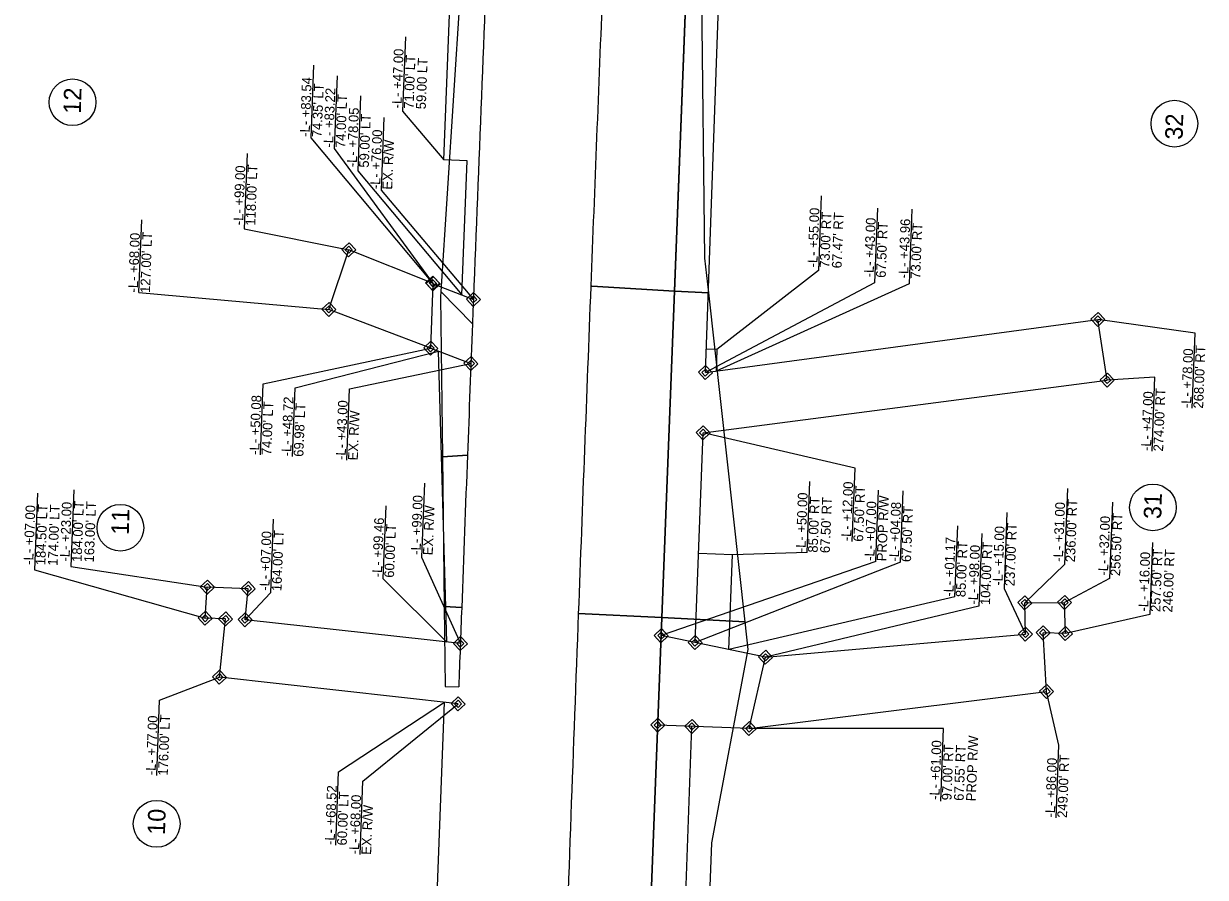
# Model space of a CAD drawing. Extents: x 2097272 to 2098144, y 685104 to 689282.
# Drawn here: x 2097469 to 2098076, y 687399 to 687838 of the extents above; entities that cross this region are included whole.
import ezdxf

# ---------------------------------------------------------------- set-up
doc = ezdxf.new("R2010")
doc.units = 0
for name, color, linetype in [('Prop Easement Construction', 7, 'Continuous'), ('Prop Easement Construction Station Offsets', 7, 'Continuous'), ('Prop Easement Permanent Drainage Utility', 7, 'Continuous'), ('Prop Easement Permanent Drainage Utility Station Offsets', 7, 'Continuous'), ('Prop Easement Permanent Utility', 7, 'Continuous'), ('Prop Easement Permanent Utility Station Offsets', 7, 'Continuous'), ('Prop Parcel Number CELL', 7, 'Continuous'), ('Prop ROW Marker CELL', 7, 'Continuous'), ('Prop ROW Permanent Easement CELL', 7, 'Continuous'), ('Prop ROW RW Lines', 7, 'Continuous'), ('Scratch_Level_3', 7, 'Continuous'), ('Scratch_Level_6', 7, 'Continuous')]:
    doc.layers.add(name, color=color, linetype=linetype)

msp = doc.modelspace()

# ---------------------------------------------------------------- linework, layer by layer
at = {"layer": 'Prop Easement Construction'}
for p, q in [((2097685.03, 687767.87), (2097689.17, 687875.79)), ((2097697.02, 687767.41), (2097685.03, 687767.87)), ((2097694.38, 687698.51), (2097697.02, 687767.41)), ((2097825.4, 687670.42), (2097819.87, 687670.63)), ((2097686.53, 687520.09), (2097682.28, 687669.63)), ((2097825.4, 687670.42), (2097824.97, 687659.39)), ((2097833.37, 687565.03), (2097815.88, 687565.7)), ((2097831.49, 687516.24), (2097833.37, 687565.03)), ((2097669.31, 687070.96), (2097685.35, 687489.17))]:
    msp.add_line(p, q, dxfattribs=at)
at = {"layer": 'Prop Easement Construction Station Offsets'}
for p, q in [((2097665.28, 687831.2), (2097663.81, 687792.87)), ((2097642.28, 687800.87), (2097640.8, 687762.32)), ((2097663.81, 687792.87), (2097685.03, 687767.87)), ((2097640.8, 687762.32), (2097694.38, 687698.51)), ((2097879.01, 687749.5), (2097877.54, 687711.11)), ((2097925.58, 687742.64), (2097924.11, 687704.25)), ((2097877.54, 687711.11), (2097825.4, 687670.42)), ((2097924.11, 687704.25), (2097824.97, 687659.39)), ((2097608.58, 687650.77), (2097682.28, 687669.63)), ((2097607.23, 687615.48), (2097608.58, 687650.77)), ((2097871.71, 687566.17), (2097873.11, 687602.61)), ((2097655.21, 687590.14), (2097653.78, 687552.81)), ((2097947.71, 687543.32), (2097949.11, 687579.77)), ((2097871.71, 687566.16), (2097833.37, 687565.03)), ((2097653.78, 687552.81), (2097686.53, 687520.09)), ((2097947.71, 687543.32), (2097831.49, 687516.24)), ((2097630.97, 687453.42), (2097685.35, 687489.17)), ((2097629.52, 687415.74), (2097630.97, 687453.42))]:
    msp.add_line(p, q, dxfattribs=at)
at = {"layer": 'Prop Easement Permanent Drainage Utility'}
for p, q in [((2097678.32, 687671.14), (2097679.59, 687704.25)), ((2097679.59, 687704.25), (2097700.26, 687696.23)), ((2097678.32, 687671.14), (2097698.98, 687663.26)), ((2097850.36, 687512.34), (2097796.74, 687523.41)), ((2097841.95, 687475.64), (2097850.36, 687512.34)), ((2097841.95, 687475.64), (2097794.98, 687477.44))]:
    msp.add_line(p, q, dxfattribs=at)
at = {"layer": 'Prop Easement Permanent Drainage Utility Station Offsets'}
for p, q in [((2097630.19, 687811.06), (2097628.75, 687773.67)), ((2097654.27, 687789.66), (2097652.83, 687752.27)), ((2097628.75, 687773.67), (2097679.59, 687704.25)), ((2097652.83, 687752.27), (2097700.26, 687696.23)), ((2097592.17, 687652.87), (2097678.32, 687671.14)), ((2097636.58, 687650.21), (2097698.98, 687663.26)), ((2097590.77, 687616.27), (2097592.17, 687652.87)), ((2097635.18, 687613.61), (2097636.58, 687650.21)), ((2097907.09, 687561.76), (2097908.49, 687598.2)), ((2097961.45, 687575.99), (2097960.02, 687538.56)), ((2097907.08, 687561.52), (2097796.74, 687523.41)), ((2097960.02, 687538.56), (2097850.36, 687512.34)), ((2097941.79, 687475.76), (2097841.95, 687475.64)), ((2097940.36, 687438.43), (2097941.79, 687475.76))]:
    msp.add_line(p, q, dxfattribs=at)
at = {"layer": 'Prop Easement Permanent Utility'}
for p, q in [((2097819.44, 687658.64), (2097827.26, 687875.5)), ((2097626.04, 687691.07), (2097636.22, 687721.7)), ((2097678.32, 687671.14), (2097626.04, 687691.07)), ((2097819.44, 687658.64), (2098021.14, 687685.93)), ((2098025.94, 687654.72), (2098021.14, 687685.93)), ((2097818.25, 687627.66), (2098025.94, 687654.72)), ((2097814.12, 687519.82), (2097818.25, 687627.66)), ((2097562.42, 687532.39), (2097563.53, 687548.36)), ((2097584.51, 687547.56), (2097563.53, 687548.36)), ((2097582.9, 687531.61), (2097584.51, 687547.56)), ((2097983.53, 687540.26), (2098004.05, 687540.47)), ((2097983.91, 687524.23), (2097983.53, 687540.26)), ((2098004.44, 687524.45), (2098004.05, 687540.47)), ((2097572.91, 687531.99), (2097562.42, 687532.39)), ((2097569.76, 687502.09), (2097572.91, 687531.99)), ((2097693.54, 687519.36), (2097582.9, 687531.61)), ((2097994.79, 687494.8), (2097992.94, 687524.89)), ((2098004.44, 687524.45), (2097992.94, 687524.89)), ((2097850.36, 687512.34), (2097983.91, 687524.23)), ((2097692.39, 687488.38), (2097569.76, 687502.09)), ((2097841.95, 687475.64), (2097994.79, 687494.8)), ((2097789.62, 686827.81), (2097812.51, 687476.77))]:
    msp.add_line(p, q, dxfattribs=at)
msp.add_lwpolyline([(2097679.59, 687704.25), (2097679.25, 687704.59), (2097636.22, 687721.7)], dxfattribs=at)
at = {"layer": 'Prop Easement Permanent Utility Station Offsets'}
for p, q in [((2097618.09, 687816.58), (2097616.66, 687779.19)), ((2097616.66, 687779.19), (2097679.25, 687704.59)), ((2097583.92, 687771.19), (2097582.44, 687732.49)), ((2097907.83, 687743.16), (2097906.36, 687704.77)), ((2097528.4, 687699.67), (2097529.83, 687737.06)), ((2097582.44, 687732.49), (2097636.22, 687721.7)), ((2097906.36, 687704.77), (2097819.44, 687658.64)), ((2097528.4, 687699.67), (2097626.04, 687691.07)), ((2098071.04, 687678.8), (2098021.14, 687685.93)), ((2098069.56, 687640.24), (2098071.04, 687678.8)), ((2098050.46, 687656.3), (2098025.94, 687654.72)), ((2098049, 687618.22), (2098050.46, 687656.3)), ((2097896.37, 687609.5), (2097818.25, 687627.66)), ((2097894.92, 687571.84), (2097896.37, 687609.5)), ((2097494.97, 687598.33), (2097493.46, 687558.91)), ((2097675.1, 687601.79), (2097673.65, 687563.82)), ((2097919.7, 687561.39), (2097921.1, 687597.84)), ((2098005.5, 687599.1), (2098004, 687559.95)), ((2097476.31, 687596.65), (2097474.8, 687557.22)), ((2098028.66, 687591.97), (2098027.16, 687552.83)), ((2097974.4, 687586.78), (2097972.9, 687547.63)), ((2097597.38, 687583.31), (2097595.93, 687545.34)), ((2098049.2, 687571.26), (2098047.78, 687534.36)), ((2097673.65, 687563.82), (2097693.54, 687519.36)), ((2097919.69, 687561.16), (2097814.12, 687519.82)), ((2097474.8, 687557.22), (2097562.42, 687532.39)), ((2097493.46, 687558.91), (2097563.53, 687548.36)), ((2098004, 687559.95), (2097983.53, 687540.26)), ((2098027.16, 687552.83), (2098004.05, 687540.47)), ((2097595.93, 687545.34), (2097582.9, 687531.61)), ((2097972.9, 687547.63), (2097983.91, 687524.23)), ((2098047.78, 687534.36), (2098004.44, 687524.45)), ((2097539.01, 687490.2), (2097569.76, 687502.09)), ((2098001.06, 687467.11), (2097994.79, 687494.8)), ((2097537.53, 687451.61), (2097539.01, 687490.2)), ((2097643.48, 687448.63), (2097692.39, 687488.38)), ((2097999.63, 687429.88), (2098001.06, 687467.11)), ((2097642.04, 687410.95), (2097643.48, 687448.63))]:
    msp.add_line(p, q, dxfattribs=at)
at = {"layer": 'Prop Parcel Number CELL'}
for centre in [(2097494.26, 687797.52), (2098060.47, 687786.52), (2098049.41, 687589.33), (2097518.84, 687578.87), (2097537.49, 687426.71)]:
    msp.add_circle(centre, 12, dxfattribs=at)
at = {"layer": 'Prop ROW Marker CELL'}
for p, q in [((2097636.22, 687721.7), (2097636.22, 687721.7)), ((2097679.25, 687704.59), (2097679.25, 687704.59)), ((2097626.04, 687691.07), (2097626.04, 687691.07)), ((2098021.14, 687685.93), (2098021.14, 687685.93)), ((2097819.44, 687658.64), (2097819.44, 687658.64)), ((2098025.94, 687654.72), (2098025.94, 687654.72)), ((2097563.53, 687548.36), (2097563.53, 687548.36)), ((2097584.51, 687547.56), (2097584.51, 687547.56)), ((2097983.53, 687540.26), (2097983.53, 687540.26)), ((2098004.05, 687540.47), (2098004.05, 687540.47)), ((2097562.42, 687532.39), (2097562.42, 687532.39)), ((2097572.91, 687531.99), (2097572.91, 687531.99)), ((2097582.9, 687531.61), (2097582.9, 687531.61)), ((2097992.94, 687524.89), (2097992.94, 687524.89)), ((2097693.54, 687519.36), (2097693.54, 687519.36)), ((2097796.74, 687523.41), (2097796.74, 687523.41)), ((2097814.12, 687519.82), (2097814.12, 687519.82)), ((2097983.91, 687524.23), (2097983.91, 687524.23)), ((2098004.44, 687524.45), (2098004.44, 687524.45)), ((2097850.36, 687512.34), (2097850.36, 687512.34)), ((2097569.76, 687502.09), (2097569.76, 687502.09)), ((2097994.79, 687494.8), (2097994.79, 687494.8)), ((2097692.39, 687488.38), (2097692.39, 687488.38)), ((2097794.98, 687477.44), (2097794.98, 687477.44)), ((2097812.51, 687476.77), (2097812.51, 687476.77)), ((2097841.95, 687475.64), (2097841.95, 687475.64))]:
    msp.add_line(p, q, dxfattribs=at)
at = {"layer": 'Prop ROW Permanent Easement CELL'}
for p, q in [((2097679.59, 687704.25), (2097679.59, 687704.25)), ((2097700.26, 687696.23), (2097700.26, 687696.23)), ((2097678.32, 687671.14), (2097678.32, 687671.14)), ((2097698.98, 687663.26), (2097698.98, 687663.26)), ((2097818.25, 687627.66), (2097818.25, 687627.66))]:
    msp.add_line(p, q, dxfattribs=at)
for points in [[(2097632.63, 687721.81), (2097636.33, 687725.3), (2097639.82, 687721.6), (2097636.12, 687718.11)], [(2097634.43, 687721.76), (2097636.28, 687723.5), (2097638.02, 687721.65), (2097636.17, 687719.91)], [(2097675.66, 687704.69), (2097679.36, 687708.18), (2097682.85, 687704.48), (2097679.15, 687700.99)], [(2097675.99, 687704.35), (2097679.69, 687707.85), (2097683.19, 687704.14), (2097679.48, 687700.65)], [(2097677.46, 687704.64), (2097679.31, 687706.39), (2097681.05, 687704.53), (2097679.2, 687702.79)], [(2097677.79, 687704.3), (2097679.64, 687706.05), (2097681.39, 687704.19), (2097679.54, 687702.45)], [(2097696.66, 687696.34), (2097700.36, 687699.83), (2097703.85, 687696.13), (2097700.15, 687692.63)], [(2097698.46, 687696.28), (2097700.31, 687698.03), (2097702.05, 687696.18), (2097700.2, 687694.43)], [(2097622.44, 687691.18), (2097626.15, 687694.67), (2097629.64, 687690.97), (2097625.94, 687687.47)], [(2097624.24, 687691.12), (2097626.1, 687692.87), (2097627.84, 687691.02), (2097625.99, 687689.27)], [(2098017.54, 687686.03), (2098021.24, 687689.53), (2098024.73, 687685.82), (2098021.03, 687682.33)], [(2098019.34, 687685.98), (2098021.19, 687687.73), (2098022.93, 687685.87), (2098021.08, 687684.13)], [(2097674.72, 687671.24), (2097678.42, 687674.74), (2097681.92, 687671.03), (2097678.21, 687667.54)], [(2097676.52, 687671.19), (2097678.37, 687672.94), (2097680.12, 687671.08), (2097678.27, 687669.34)], [(2097695.38, 687663.36), (2097699.09, 687666.85), (2097702.58, 687663.15), (2097698.88, 687659.66)], [(2097697.18, 687663.31), (2097699.04, 687665.06), (2097700.78, 687663.2), (2097698.93, 687661.46)], [(2097815.84, 687658.74), (2097819.55, 687662.23), (2097823.04, 687658.53), (2097819.34, 687655.04)], [(2097817.64, 687658.69), (2097819.49, 687660.44), (2097821.24, 687658.58), (2097819.39, 687656.84)], [(2098022.35, 687654.82), (2098026.05, 687658.32), (2098029.54, 687654.62), (2098025.84, 687651.12)], [(2098024.14, 687654.77), (2098026, 687656.52), (2098027.74, 687654.67), (2098025.89, 687652.92)], [(2097814.66, 687627.76), (2097818.36, 687631.26), (2097821.85, 687627.56), (2097818.15, 687624.06)], [(2097816.45, 687627.71), (2097818.31, 687629.46), (2097820.05, 687627.61), (2097818.2, 687625.86)], [(2097559.93, 687548.47), (2097563.63, 687551.96), (2097567.13, 687548.26), (2097563.42, 687544.76)], [(2097561.73, 687548.42), (2097563.58, 687550.16), (2097565.33, 687548.31), (2097563.48, 687546.56)], [(2097580.91, 687547.66), (2097584.62, 687551.16), (2097588.11, 687547.45), (2097584.41, 687543.96)], [(2097582.71, 687547.61), (2097584.57, 687549.36), (2097586.31, 687547.51), (2097584.46, 687545.76)], [(2097979.93, 687540.37), (2097983.63, 687543.86), (2097987.12, 687540.16), (2097983.42, 687536.66)], [(2098000.45, 687540.58), (2098004.15, 687544.07), (2098007.65, 687540.37), (2098003.95, 687536.88)], [(2097981.73, 687540.31), (2097983.58, 687542.06), (2097985.32, 687540.21), (2097983.47, 687538.46)], [(2098002.25, 687540.53), (2098004.1, 687542.27), (2098005.85, 687540.42), (2098004, 687538.68)], [(2097558.82, 687532.5), (2097562.52, 687535.99), (2097566.01, 687532.29), (2097562.31, 687528.8)], [(2097560.62, 687532.45), (2097562.47, 687534.19), (2097564.21, 687532.34), (2097562.36, 687530.59)], [(2097569.31, 687532.1), (2097573.01, 687535.59), (2097576.51, 687531.89), (2097572.8, 687528.39)], [(2097571.11, 687532.04), (2097572.96, 687533.79), (2097574.71, 687531.94), (2097572.86, 687530.19)], [(2097579.3, 687531.71), (2097583.01, 687535.21), (2097586.5, 687531.5), (2097582.8, 687528.01)], [(2097581.1, 687531.66), (2097582.95, 687533.41), (2097584.7, 687531.56), (2097582.85, 687529.81)], [(2097793.14, 687523.51), (2097796.85, 687527.01), (2097800.34, 687523.3), (2097796.64, 687519.81)], [(2097794.94, 687523.46), (2097796.8, 687525.21), (2097798.54, 687523.35), (2097796.69, 687521.61)], [(2097980.31, 687524.34), (2097984.02, 687527.83), (2097987.51, 687524.13), (2097983.81, 687520.64)], [(2097982.11, 687524.29), (2097983.96, 687526.03), (2097985.71, 687524.18), (2097983.86, 687522.44)], [(2097989.35, 687524.99), (2097993.05, 687528.49), (2097996.54, 687524.78), (2097992.84, 687521.29)], [(2097991.14, 687524.94), (2097993, 687526.69), (2097994.74, 687524.84), (2097992.89, 687523.09)], [(2098000.84, 687524.55), (2098004.54, 687528.05), (2098008.03, 687524.34), (2098004.33, 687520.85)], [(2098002.64, 687524.5), (2098004.49, 687526.25), (2098006.23, 687524.4), (2098004.38, 687522.65)], [(2097689.94, 687519.46), (2097693.64, 687522.96), (2097697.14, 687519.25), (2097693.43, 687515.76)], [(2097691.74, 687519.41), (2097693.59, 687521.16), (2097695.34, 687519.31), (2097693.49, 687517.56)], [(2097810.52, 687519.93), (2097814.22, 687523.42), (2097817.72, 687519.72), (2097814.01, 687516.22)], [(2097812.32, 687519.87), (2097814.17, 687521.62), (2097815.92, 687519.77), (2097814.07, 687518.02)], [(2097846.76, 687512.45), (2097850.46, 687515.94), (2097853.96, 687512.24), (2097850.25, 687508.75)], [(2097848.56, 687512.4), (2097850.41, 687514.14), (2097852.16, 687512.29), (2097850.31, 687510.54)], [(2097566.16, 687502.19), (2097569.86, 687505.69), (2097573.36, 687501.99), (2097569.66, 687498.49)], [(2097567.96, 687502.14), (2097569.81, 687503.89), (2097571.56, 687502.04), (2097569.71, 687500.29)], [(2097991.19, 687494.9), (2097994.9, 687498.39), (2097998.39, 687494.69), (2097994.69, 687491.2)], [(2097992.99, 687494.85), (2097994.84, 687496.6), (2097996.59, 687494.74), (2097994.74, 687493)], [(2097688.79, 687488.49), (2097692.49, 687491.98), (2097695.99, 687488.28), (2097692.28, 687484.78)], [(2097690.59, 687488.43), (2097692.44, 687490.18), (2097694.19, 687488.33), (2097692.34, 687486.58)], [(2097791.38, 687477.55), (2097795.08, 687481.04), (2097798.58, 687477.34), (2097794.88, 687473.84)], [(2097793.18, 687477.49), (2097795.03, 687479.24), (2097796.78, 687477.39), (2097794.93, 687475.64)], [(2097808.91, 687476.87), (2097812.62, 687480.37), (2097816.11, 687476.66), (2097812.41, 687473.17)], [(2097810.71, 687476.82), (2097812.56, 687478.57), (2097814.31, 687476.72), (2097812.46, 687474.97)], [(2097838.35, 687475.74), (2097842.05, 687479.24), (2097845.54, 687475.54), (2097841.84, 687472.04)], [(2097840.15, 687475.69), (2097842, 687477.44), (2097843.74, 687475.59), (2097841.89, 687473.84)]]:
    msp.add_lwpolyline(points, close=True, dxfattribs=at)
at = {"layer": 'Prop ROW RW Lines'}
msp.add_line((2097775.94, 686980.56), (2097815.64, 688016.04), dxfattribs=at)
at = {"layer": 'Scratch_Level_3'}
for p, q in [((2097803.54, 687700.51), (2097809.42, 687853.94)), ((2097760.56, 687702.99), (2097761.1, 687702.95)), ((2097761.1, 687702.95), (2097760.56, 687702.99)), ((2097761.1, 687702.95), (2097803.54, 687700.51)), ((2097803.54, 687700.51), (2097761.1, 687702.95)), ((2097797.1, 687532.67), (2097803.54, 687700.51)), ((2097754.16, 687534.79), (2097797.1, 687532.67)), ((2097797.1, 687532.67), (2097754.16, 687534.79)), ((2097776.58, 686997.78), (2097797.1, 687532.67))]:
    msp.add_line(p, q, dxfattribs=at)
for start, end in [(177.7042161, 177.7780686), (177.7780686, 177.8592491), (177.8592491, 177.9594601)]:
    msp.add_arc((2216468.39, 683097.18), 118797.14, start, end, dxfattribs=at)
at = {"layer": 'Scratch_Level_6'}
for p, q in [((2097695.97, 687891.79), (2097683.51, 687700.25)), ((2097809.42, 687853.94), (2097803.54, 687700.51)), ((2097819.19, 687717.38), (2097817.61, 687853.54)), ((2097821.18, 687699.5), (2097819.19, 687717.38)), ((2097683.51, 687700.25), (2097683.33, 687697.57)), ((2097683.33, 687697.57), (2097684.29, 687615.29)), ((2097699.77, 687683.69), (2097683.51, 687700.25)), ((2097683.51, 687700.25), (2097699.77, 687683.69)), ((2097803.54, 687700.51), (2097797.1, 687532.67)), ((2097803.54, 687700.51), (2097821.18, 687699.5)), ((2097821.18, 687699.5), (2097803.54, 687700.51)), ((2097839.93, 687530.55), (2097821.18, 687699.5)), ((2097697.18, 687616.14), (2097684.29, 687615.29)), ((2097684.29, 687615.29), (2097697.18, 687616.14)), ((2097684.29, 687615.29), (2097685.19, 687538.36)), ((2097694.23, 687537.8), (2097685.19, 687538.36)), ((2097685.19, 687538.36), (2097685.66, 687497.33)), ((2097685.19, 687538.36), (2097694.23, 687537.8)), ((2097797.1, 687532.67), (2097776.58, 686997.78)), ((2097797.1, 687532.67), (2097839.93, 687530.55)), ((2097839.93, 687530.55), (2097797.1, 687532.67)), ((2097841.51, 687516.38), (2097839.93, 687530.55)), ((2097822.69, 687417.02), (2097841.51, 687516.38)), ((2097685.66, 687497.33), (2097692.71, 687497.06)), ((2097818.85, 687317.1), (2097822.69, 687417.02))]:
    msp.add_line(p, q, dxfattribs=at)
for start, end in [(177.6883627, 177.7884999), (177.7884999, 177.8210849), (177.8210849, 177.8588768), (177.8588768, 177.8785279)]:
    msp.add_arc((2216468.39, 683097.18), 118857.14, start, end, dxfattribs=at)

# ---------------------------------------------------------------- texts
at = {"layer": 'Prop Easement Construction Station Offsets'}
for s, p in [('-L- +47.00', (2097663.24, 687794.31)), ("71.00' LT", (2097669.48, 687794.07)), ('59.00 LT', (2097675.73, 687793.83)), ('-L- +78.05', (2097640.24, 687764.05)), ("59.00' LT", (2097646.48, 687763.81)), ('-L- +55.00', (2097876.92, 687712.57)), ("73.00' RT", (2097883.16, 687712.33)), ("67.47' RT", (2097889.41, 687712.09)), ('-L- +43.96', (2097923.59, 687706.95)), ("73.00' RT", (2097929.83, 687706.71)), ('-L- +48.72', (2097606.6, 687615.5)), ("69.98' LT", (2097612.85, 687615.26)), ('-L- +50.00', (2097870.86, 687566.23)), ("85.00' RT", (2097877.11, 687565.99)), ("67.50' RT", (2097883.35, 687565.75)), ('-L- +99.46', (2097653.18, 687553.35)), ("60.00' LT", (2097659.42, 687553.11)), ('-L- +01.17', (2097946.83, 687543.36)), ("85.00' RT", (2097953.08, 687543.12)), ('-L- +68.52', (2097628.9, 687415.77)), ("60.00' LT", (2097635.14, 687415.53))]:
    msp.add_text(s, height=5, rotation=87.8037, dxfattribs=at).set_placement(p)
at = {"layer": 'Prop Easement Permanent Drainage Utility Station Offsets'}
for s, p in [('-L- +83.22', (2097628.15, 687774.17)), ("74.00' LT", (2097634.39, 687773.93)), ('-L- +76.00', (2097652.23, 687752.77)), ('EX. R/W', (2097658.47, 687752.53)), ('-L- +50.08', (2097590.14, 687616.29)), ("74.00' LT", (2097596.39, 687616.06)), ('-L- +43.00', (2097634.55, 687613.64)), ('EX. R/W', (2097640.8, 687613.4)), ('-L- +07.00', (2097906.22, 687561.79)), ('PROP R/W', (2097912.46, 687561.55)), ('-L- +98.00', (2097959.42, 687539.32)), ("104.00' RT", (2097965.67, 687539.08)), ('PROP R/W', (2097958.38, 687438.22)), ('-L- +61.00', (2097939.64, 687438.93)), ("97.00' RT", (2097945.89, 687438.69)), ("67.55' RT", (2097952.14, 687438.46))]:
    msp.add_text(s, height=5, rotation=87.8037, dxfattribs=at).set_placement(p)
at = {"layer": 'Prop Easement Permanent Utility Station Offsets'}
for s, p in [('-L- +83.54', (2097616.05, 687779.69)), ("74.35' LT", (2097622.3, 687779.45)), ('-L- +99.00', (2097581.88, 687734.3)), ("118.00' LT", (2097588.13, 687734.06)), ('-L- +43.00', (2097905.84, 687707.47)), ("67.50' RT", (2097912.08, 687707.23)), ('-L- +68.00', (2097527.77, 687699.7)), ("127.00' LT", (2097534.02, 687699.46)), ('-L- +78.00', (2098068.94, 687640.27)), ("268.00' RT", (2098075.18, 687640.03)), ('-L- +47.00', (2098048.38, 687618.24)), ("274.00' RT", (2098054.62, 687618)), ('-L- +12.00', (2097894.24, 687571.86)), ("67.50' RT", (2097900.48, 687571.62)), ('-L- +23.00', (2097492.69, 687561.45)), ("184.00' LT", (2097498.93, 687561.21)), ("163.00' LT", (2097505.18, 687560.97)), ('-L- +99.00', (2097673.06, 687564.9)), ('-L- +04.08', (2097918.83, 687561.42)), ('-L- +31.00', (2098003.12, 687561.32)), ("236.00' RT", (2098009.37, 687561.08)), ('-L- +07.00', (2097474.03, 687559.77)), ("184.50' LT", (2097480.27, 687559.53)), ("174.00' LT", (2097486.52, 687559.29)), ('EX. R/W', (2097679.31, 687564.66)), ("67.50' RT", (2097925.07, 687561.18)), ("256.50' RT", (2098032.53, 687553.96)), ('-L- +15.00', (2097972.03, 687549)), ("237.00' RT", (2097978.27, 687548.76)), ('-L- +32.00', (2098026.28, 687554.2)), ('-L- +07.00', (2097595.34, 687546.42)), ("164.00' LT", (2097601.59, 687546.18)), ("257.50' RT", (2098053.13, 687535.49)), ("246.00' RT", (2098059.38, 687535.25)), ('-L- +16.00', (2098046.89, 687535.73)), ("176.00' LT", (2097543.16, 687451.4)), ('-L- +77.00', (2097536.91, 687451.64)), ('-L- +86.00', (2097999, 687429.91)), ("249.00' RT", (2098005.25, 687429.67)), ('-L- +68.00', (2097641.41, 687410.97)), ('EX. R/W', (2097647.66, 687410.73))]:
    msp.add_text(s, height=5, rotation=87.8037, dxfattribs=at).set_placement(p)
at = {"layer": 'Prop Parcel Number CELL'}
for s, p in [('12', (2097498.52, 687791.52)), ('32', (2098064.65, 687778.18)), ('31', (2098053.66, 687583.23)), ('11', (2097523.15, 687575.1)), ('10', (2097541.75, 687420.95))]:
    msp.add_text(s, height=9, rotation=88.33483, dxfattribs=at).set_placement(p)

doc.saveas('drawing.dxf')
